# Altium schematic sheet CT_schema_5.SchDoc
size 312 x 277 mm
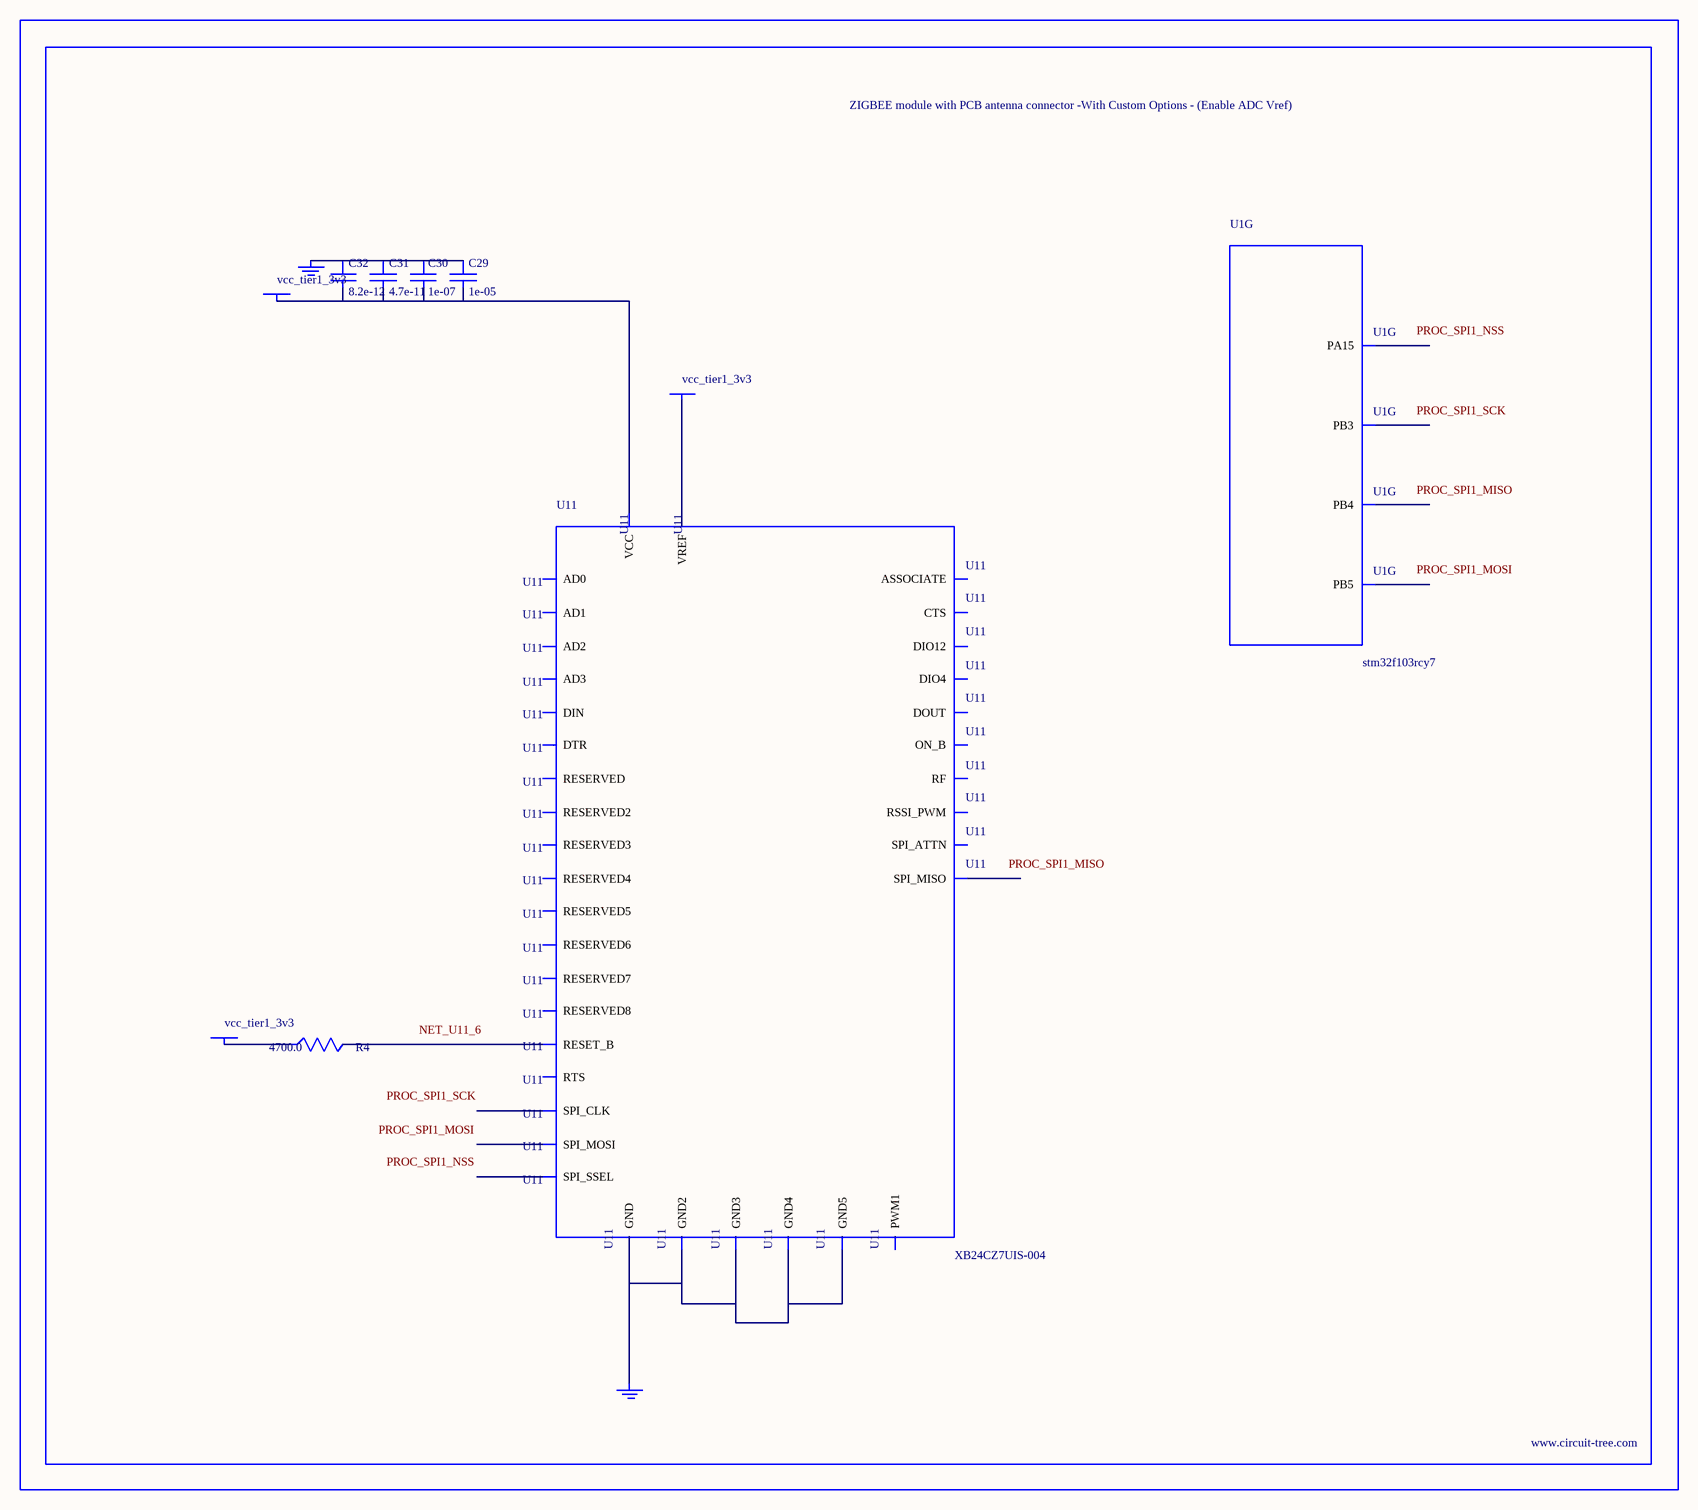
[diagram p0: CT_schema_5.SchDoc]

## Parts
BORDER4  (no value)
C29  1e-05  [C0805]
C30  1e-07  [C0402]
C31  4.7e-11  [C0402]
C32  8.2e-12  [C0603]
GND_INSTANCE_4_0  (no value)
GND_INSTANCE_4_1  (no value)
POWER_INSTANCE_4_0  vcc_tier1_3v3
POWER_INSTANCE_4_1  vcc_tier1_3v3
POWER_INSTANCE_4_2  vcc_tier1_3v3
R4  4700.0  [R0603]
U1  stm32f103rcy7  [WLCSP64]  (part G of 7)
U11  XB24CZ7UIS-004  [XB24CZ7UIS-004]

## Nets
NetC29_1: C29.1 C30.1 C31.1 C32.1 GND_INSTANCE_4_0.0(GND)
NetC29_2: C29.2 C30.2 C31.2 C32.2 POWER_INSTANCE_4_0.0(PWR) U11.2(VCC)
NetGND_INSTANCE_4_1_0: GND_INSTANCE_4_1.0(GND) U11.1(GND) U11.11(GND2) U11.13(GND3) U11.22(GND4) U11.35(GND5)
NetPOWER_INSTANCE_4_1_0: POWER_INSTANCE_4_1.0(PWR) R4.1
NetPOWER_INSTANCE_4_2_0: POWER_INSTANCE_4_2.0(PWR) U11.27(VREF)
NetR4_2: R4.2 U11.6(RESET_B)

Not connected (* = marked no-connect by the designer): U1 A4(PB3) A5(PB5) B4(PB4) C3(PA15); U11 3(DOUT) 4(DIN) 5(DIO12) 7(RSSI_PWM) 8(PWM1) 9(RESERVED) 10(DTR) 12(SPI_ATTN) 14(SPI_CLK) 15(SPI_SSEL) 16(SPI_MOSI) 17(SPI_MISO) 18(RESERVED2) 19(RESERVED3) 20(RESERVED4) 21(RESERVED5) 23(RESERVED6) 24(DIO4) 25(CTS) 26(ON_B) 28(ASSOCIATE) 29(RTS) 30(AD3) 31(AD2) 32(AD1) 33(AD0) 34(RESERVED7) 36(RF) 37(RESERVED8)

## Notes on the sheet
- Labels drawn without touching a wire or pin: NET_U11_6, PROC_SPI1_MISO, PROC_SPI1_MOSI, PROC_SPI1_NSS, PROC_SPI1_SCK

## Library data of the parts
BORDER4 = BORDER_PAGE4
C29 = C0805C106K8RACTU
C30 = C0402C104K3RACTU
C31 = C0402C470K3RAC
C32 = 06035J8R2BBTTR
GND_INSTANCE_4_0 GND_INSTANCE_4_1 = GND
POWER_INSTANCE_4_0-POWER_INSTANCE_4_2 = PWR
R4 = RC0603JR-074K7L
